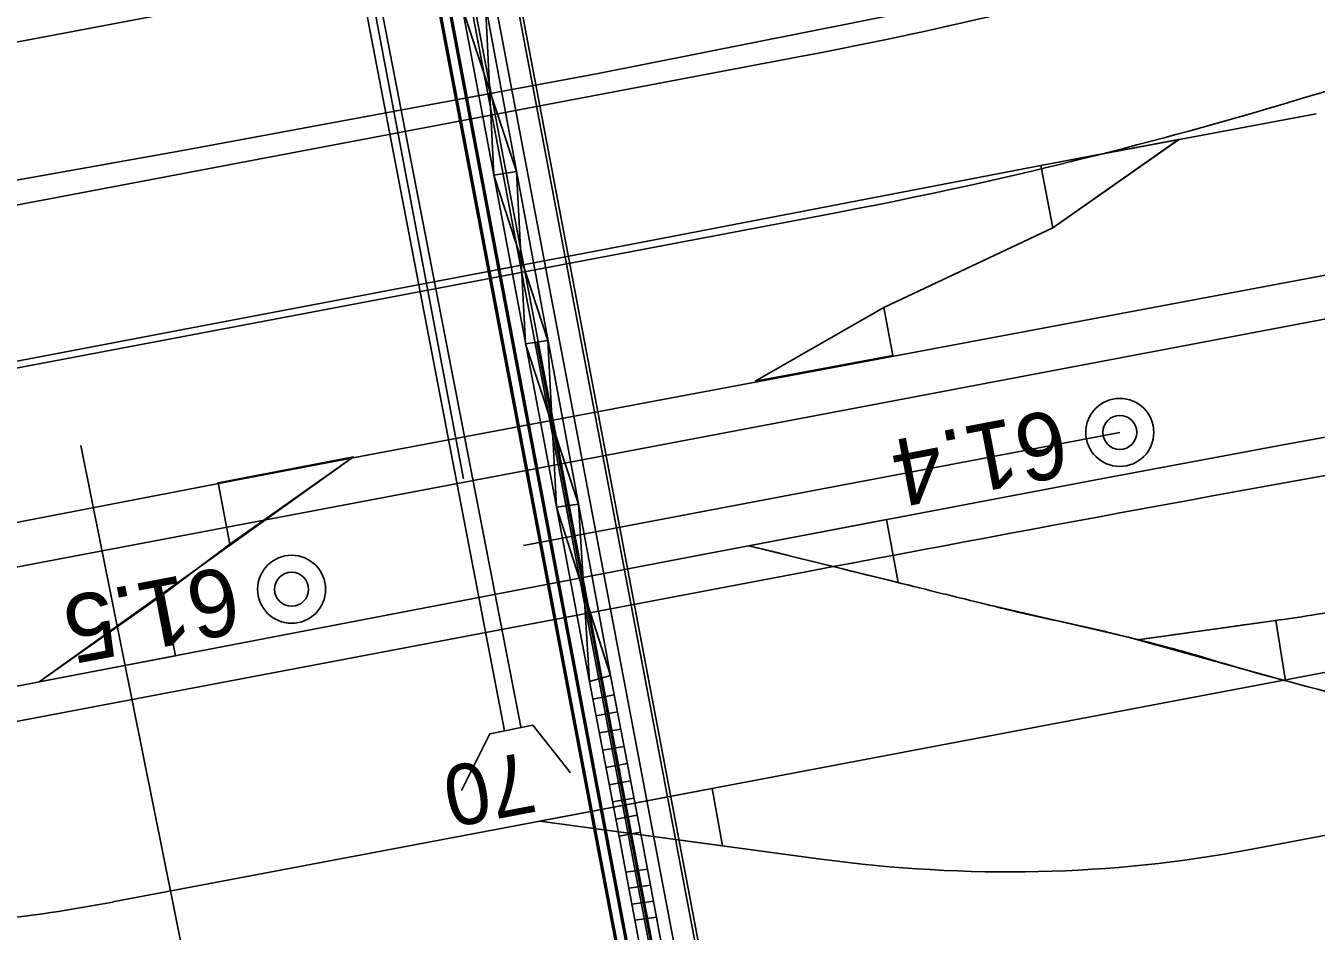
# Model space of a CAD drawing. Extents: x 6541740 to 6566395, y 5525066 to 5530361.
# Drawn here: x 6557192.81 to 6557231.08, y 5526153.77 to 5526180.64 of the extents above; entities that cross this region are included whole.
import ezdxf

# ---------------------------------------------------------------- set-up
doc = ezdxf.new("R2010")
doc.units = 0
for name, color, linetype in [('Domyślna', 7, 'Continuous'), ('TOR_PRZEK_P-komponent', 7, 'Continuous'), ('TOR_PS_OPIS_O-opisy odwodnienia', 7, 'Continuous'), ('TOR_PS_OPIS_T-opis geometrii-wzdluz_cz torowa', 7, 'Continuous'), ('TOR_PS_T-rowy otwarte nieumocnione', 7, 'Continuous'), ('TOR_PS_T-umocnienia skarp', 7, 'Continuous'), ('TOR_RAMKI-ramka+tabelka 1', 7, 'Continuous'), ('TOR_W-warstwa dodatkowa 2', 7, 'Continuous')]:
    doc.layers.add(name, color=color, linetype=linetype)

# ---------------------------------------------------------------- blocks, each defined once
blk = doc.blocks.new('4010_1')
at = {"layer": 'Domyślna'}
for radius in [0.75, 0.375]:
    blk.add_circle((0, 0), radius, dxfattribs=at)

msp = doc.modelspace()

# ---------------------------------------------------------------- linework, layer by layer
at = {"layer": 'Domyślna'}
for p, q in [((6557200.158, 5526195.418), (6557207.01, 5526159.72)), ((6557207.492, 5526159.837), (6557200.574, 5526195.475))]:
    msp.add_line(p, q, dxfattribs=at)
msp.add_lwpolyline([(6557205.727, 5526157.942), (6557206.569, 5526159.63), (6557207.846, 5526159.89), (6557208.96, 5526158.467)], dxfattribs=at)
at = {"layer": 'TOR_PRZEK_P-komponent'}
for p, q in [((6557416.454, 5526207.025), (6557145.327, 5526155.632)), ((6557212.028, 5526183.848), (6557116.502, 5526165.741)), ((6557019.224, 5526142.467), (6557215.881, 5526179.744)), ((6557102.514, 5526153.42), (6557216.785, 5526175.081)), ((6557216.049, 5526164.458), (6556955.024, 5526114.98)), ((6557233.026, 5526161.773), (6557208.044, 5526157.037)), ((6557213.164, 5526158.008), (6557208.055, 5526157.039)), ((6557213.164, 5526158.008), (6557208.055, 5526157.039)), ((6557235.525, 5526157.412), (6557229.122, 5526156.198)), ((6557208.055, 5526157.039), (6557195.39, 5526154.639)), ((6557216.392, 5526155.912), (6557208.055, 5526157.039)), ((6557216.392, 5526155.912), (6557208.055, 5526157.039))]:
    msp.add_line(p, q, dxfattribs=at)
msp.add_lwpolyline([(6557208.055, 5526157.039), (6557213.468, 5526156.307), (6557213.164, 5526158.008)], dxfattribs=at)
msp.add_lwpolyline([(6557208.055, 5526157.039), (6557213.468, 5526156.307), (6557213.164, 5526158.008)], dxfattribs=at)
msp.add_arc((6557599.6, 5524141.009), 2059.479, 100.137444, 100.733239, dxfattribs=at)
for centre, major_axis, start_param, end_param in [((6556815.472, 5528292.13), (-400.409, 2112.386), 3.141593, 3.189176), ((6556816.376, 5528287.466), (-400.409, 2112.386), 3.141593, 3.189174), ((6557116.449, 5526750.613), (-112.673, 594.415), 3.058451, 3.141593), ((6557053.85, 5526901.342), (-141.54, 746.704), 3.102175, 3.141593)]:
    msp.add_ellipse(centre, major_axis=major_axis, ratio=0.25, start_param=start_param, end_param=end_param, dxfattribs=at)
at = {"layer": 'TOR_PS_OPIS_T-opis geometrii-wzdluz_cz torowa'}
for p, q in [((6557205.793, 5526167.193), (6557195.226, 5526222.944)), ((6557207.965, 5526171.251), (6557218.533, 5526115.501)), ((6557225.255, 5526168.573), (6557207.57, 5526165.221)), ((6557194.444, 5526168.185), (6557200.689, 5526137.091)), ((6557194.444, 5526168.185), (6557200.689, 5526137.091))]:
    msp.add_line(p, q, dxfattribs=at)
at = {"layer": 'TOR_PS_T-rowy otwarte nieumocnione'}
for p, q in [((6557231.08, 5526178.023), (6557222.914, 5526176.494)), ((6557231.08, 5526178.023), (6557222.914, 5526176.494)), ((6557226.997, 5526177.259), (6557223.266, 5526174.643)), ((6557226.997, 5526177.259), (6557223.266, 5526174.643)), ((6557223.266, 5526174.643), (6557226.997, 5526177.258)), ((6557223.266, 5526174.643), (6557226.997, 5526177.258)), ((6557214.443, 5526170.092), (6557218.253, 5526172.279)), ((6557214.443, 5526170.092), (6557218.253, 5526172.279)), ((6557214.443, 5526170.092), (6557218.253, 5526172.279)), ((6557214.443, 5526170.092), (6557218.253, 5526172.279)), ((6557202.533, 5526167.843), (6557198.857, 5526165.253)), ((6557202.533, 5526167.843), (6557198.857, 5526165.253)), ((6557193.205, 5526161.17), (6557196.897, 5526163.774)), ((6557193.205, 5526161.17), (6557196.897, 5526163.774)), ((6557225.793, 5526162.417), (6557229.886, 5526162.994)), ((6557225.793, 5526162.417), (6557229.886, 5526162.994))]:
    msp.add_line(p, q, dxfattribs=at)
for points in [[(6557246.51, 5526186.462), (6557234.231, 5526184.137), (6557221.923, 5526181.643), (6557209.734, 5526179.216), (6557197.409, 5526176.929)], [(6557197.409, 5526176.929), (6557209.734, 5526179.216), (6557221.923, 5526181.643), (6557234.231, 5526184.137), (6557246.51, 5526186.462)], [(6557246.51, 5526186.462), (6557234.231, 5526184.137), (6557221.923, 5526181.643), (6557209.734, 5526179.216), (6557197.409, 5526176.929)], [(6557197.409, 5526176.929), (6557209.734, 5526179.216), (6557221.923, 5526181.643), (6557234.231, 5526184.137), (6557246.51, 5526186.462)], [(6557268.852, 5526180.307), (6557260.657, 5526178.76), (6557260.657, 5526178.76), (6557248.388, 5526176.45), (6557248.388, 5526176.449), (6557236.094, 5526174.13), (6557236.094, 5526174.13), (6557223.819, 5526171.819), (6557223.819, 5526171.819), (6557211.543, 5526169.52), (6557211.543, 5526169.52), (6557203.346, 5526167.976), (6557199.25, 5526167.195), (6557199.249, 5526167.195), (6557186.987, 5526164.833), (6557186.987, 5526164.833), (6557174.708, 5526162.516), (6557162.421, 5526160.185), (6557162.421, 5526160.185), (6557150.132, 5526157.846), (6557150.132, 5526157.846), (6557146.037, 5526157.053), (6557137.851, 5526155.44)], [(6557268.852, 5526180.307), (6557260.657, 5526178.76), (6557260.657, 5526178.76), (6557248.388, 5526176.45), (6557248.388, 5526176.449), (6557236.094, 5526174.13), (6557236.094, 5526174.13), (6557223.819, 5526171.819), (6557223.819, 5526171.819), (6557211.543, 5526169.52), (6557211.543, 5526169.52), (6557203.346, 5526167.976), (6557199.25, 5526167.195), (6557199.249, 5526167.195), (6557186.987, 5526164.833), (6557186.987, 5526164.833), (6557174.708, 5526162.516), (6557162.421, 5526160.185), (6557162.421, 5526160.185), (6557150.132, 5526157.846), (6557150.132, 5526157.846), (6557146.037, 5526157.053), (6557137.851, 5526155.44)], [(6557197.409, 5526176.927), (6557185.105, 5526174.736), (6557172.832, 5526172.553), (6557169.344, 5526171.884)], [(6557169.344, 5526171.884), (6557172.832, 5526172.553), (6557185.105, 5526174.736), (6557197.409, 5526176.927)], [(6557197.409, 5526176.927), (6557185.105, 5526174.736), (6557172.832, 5526172.553), (6557169.344, 5526171.884)], [(6557169.344, 5526171.884), (6557172.832, 5526172.553), (6557185.105, 5526174.736), (6557197.409, 5526176.927)], [(6557222.914, 5526176.494), (6557222.914, 5526176.493), (6557210.689, 5526174.139), (6557198.358, 5526171.792)], [(6557222.914, 5526176.494), (6557222.914, 5526176.493), (6557210.689, 5526174.139), (6557198.358, 5526171.792)], [(6557218.253, 5526172.279), (6557223.266, 5526174.643)], [(6557218.253, 5526172.279), (6557223.266, 5526174.643)], [(6557218.253, 5526172.279), (6557223.266, 5526174.643)], [(6557218.253, 5526172.279), (6557223.266, 5526174.643)], [(6557261.875, 5526172.232), (6557259.395, 5526172.099), (6557258.156, 5526172.024), (6557256.301, 5526171.899), (6557253.523, 5526171.679), (6557251.676, 5526171.509), (6557250.753, 5526171.416), (6557249.372, 5526171.266), (6557249.372, 5526171.266), (6557247.987, 5526171.103), (6557247.065, 5526170.987), (6557245.224, 5526170.74), (6557242.468, 5526170.335), (6557240.635, 5526170.047), (6557236.974, 5526169.435), (6557236.974, 5526169.435), (6557232.88, 5526168.711), (6557230.153, 5526168.213), (6557224.703, 5526167.195), (6557212.428, 5526164.865), (6557212.428, 5526164.865), (6557200.161, 5526162.505), (6557200.161, 5526162.505), (6557191.968, 5526160.933)], [(6557261.875, 5526172.232), (6557259.395, 5526172.099), (6557258.156, 5526172.024), (6557256.301, 5526171.899), (6557253.523, 5526171.679), (6557251.676, 5526171.509), (6557250.753, 5526171.416), (6557249.372, 5526171.266), (6557249.372, 5526171.266), (6557247.987, 5526171.103), (6557247.065, 5526170.987), (6557245.224, 5526170.74), (6557242.468, 5526170.335), (6557240.635, 5526170.047), (6557236.974, 5526169.435), (6557236.974, 5526169.435), (6557232.88, 5526168.711), (6557230.153, 5526168.213), (6557224.703, 5526167.195), (6557212.428, 5526164.865), (6557212.428, 5526164.865), (6557200.161, 5526162.505), (6557200.161, 5526162.505), (6557191.968, 5526160.933)], [(6557198.358, 5526171.79), (6557186.11, 5526169.456), (6557173.848, 5526167.145), (6557161.527, 5526164.811), (6557158.117, 5526164.166), (6557158.091, 5526164.161)], [(6557198.358, 5526171.79), (6557186.11, 5526169.456), (6557173.848, 5526167.145), (6557161.527, 5526164.811), (6557158.117, 5526164.166), (6557158.091, 5526164.161)], [(6557193.205, 5526161.17), (6557202.533, 5526167.843)], [(6557193.205, 5526161.17), (6557202.533, 5526167.843)], [(6557196.897, 5526163.774), (6557198.857, 5526165.253)], [(6557196.897, 5526163.774), (6557198.857, 5526165.253)], [(6557221.493, 5526163.424), (6557225.586, 5526162.474), (6557230.173, 5526161.204)], [(6557221.493, 5526163.424), (6557225.586, 5526162.474), (6557230.173, 5526161.204)]]:
    msp.add_lwpolyline(points, dxfattribs=at)
for points in [[(6557226.997, 5526177.259), (6557222.914, 5526176.494), (6557223.266, 5526174.643)], [(6557226.997, 5526177.259), (6557222.914, 5526176.494), (6557223.266, 5526174.643)], [(6557214.443, 5526170.092), (6557218.524, 5526170.857), (6557218.253, 5526172.279)], [(6557214.443, 5526170.092), (6557218.524, 5526170.857), (6557218.253, 5526172.279)], [(6557202.533, 5526167.843), (6557198.511, 5526167.076), (6557198.857, 5526165.253)], [(6557202.533, 5526167.843), (6557198.511, 5526167.076), (6557198.857, 5526165.253)], [(6557214.25, 5526165.21), (6557218.337, 5526165.986), (6557218.685, 5526164.114)], [(6557214.25, 5526165.21), (6557218.337, 5526165.986), (6557218.685, 5526164.114)], [(6557193.206, 5526161.17), (6557197.247, 5526161.946), (6557196.897, 5526163.774)], [(6557193.206, 5526161.17), (6557197.247, 5526161.946), (6557196.897, 5526163.774)], [(6557225.793, 5526162.417), (6557230.173, 5526161.204), (6557229.886, 5526162.994)], [(6557225.793, 5526162.417), (6557230.173, 5526161.204), (6557229.886, 5526162.994)]]:
    msp.add_lwpolyline(points, close=True, dxfattribs=at)
for points in [[(6557250.293, 5526166.395), (6557246.156, 5526165.835), (6557242.019, 5526165.276), (6557237.882, 5526164.716), (6557235.178, 5526164.35), (6557232.588, 5526163.375), (6557229.886, 5526162.994), (6557228.521, 5526162.802), (6557227.157, 5526162.61), (6557225.793, 5526162.417)], [(6557250.293, 5526166.395), (6557246.156, 5526165.835), (6557242.019, 5526165.276), (6557237.882, 5526164.716), (6557235.178, 5526164.35), (6557232.588, 5526163.375), (6557229.886, 5526162.994), (6557228.521, 5526162.802), (6557227.157, 5526162.61), (6557225.793, 5526162.417)], [(6557214.25, 5526165.21), (6557216.616, 5526164.626), (6557218.982, 5526164.041), (6557221.349, 5526163.456), (6557222.765, 5526163.106), (6557224.17, 5526162.828), (6557225.586, 5526162.474), (6557227.108, 5526162.095), (6557228.646, 5526161.615), (6557230.173, 5526161.204), (6557233.093, 5526160.42), (6557236.002, 5526159.7), (6557238.91, 5526158.994), (6557241.136, 5526158.453), (6557243.377, 5526157.837), (6557245.5, 5526157.898), (6557247.623, 5526157.96), (6557249.747, 5526158.022), (6557251.87, 5526158.083)], [(6557214.25, 5526165.21), (6557216.616, 5526164.626), (6557218.982, 5526164.041), (6557221.349, 5526163.456), (6557222.765, 5526163.106), (6557224.17, 5526162.828), (6557225.586, 5526162.474), (6557227.108, 5526162.095), (6557228.646, 5526161.615), (6557230.173, 5526161.204), (6557233.093, 5526160.42), (6557236.002, 5526159.7), (6557238.91, 5526158.994), (6557241.136, 5526158.453), (6557243.377, 5526157.837), (6557245.5, 5526157.898), (6557247.623, 5526157.96), (6557249.747, 5526158.022), (6557251.87, 5526158.083)], [(6557214.25, 5526165.21), (6557216.616, 5526164.626), (6557218.982, 5526164.041), (6557221.349, 5526163.456), (6557222.765, 5526163.106), (6557224.17, 5526162.828), (6557225.586, 5526162.474), (6557227.108, 5526162.095), (6557228.646, 5526161.615), (6557230.173, 5526161.204), (6557233.093, 5526160.42), (6557236.002, 5526159.7), (6557238.91, 5526158.994), (6557241.136, 5526158.453), (6557243.377, 5526157.837), (6557245.5, 5526157.898), (6557247.623, 5526157.96), (6557249.747, 5526158.022), (6557251.87, 5526158.083)], [(6557214.25, 5526165.21), (6557216.616, 5526164.626), (6557218.982, 5526164.041), (6557221.349, 5526163.456), (6557222.765, 5526163.106), (6557224.17, 5526162.828), (6557225.586, 5526162.474), (6557227.108, 5526162.095), (6557228.646, 5526161.615), (6557230.173, 5526161.204), (6557233.093, 5526160.42), (6557236.002, 5526159.7), (6557238.91, 5526158.994), (6557241.136, 5526158.453), (6557243.377, 5526157.837), (6557245.5, 5526157.898), (6557247.623, 5526157.96), (6557249.747, 5526158.022), (6557251.87, 5526158.083)], [(6557214.25, 5526165.21), (6557216.616, 5526164.626), (6557218.982, 5526164.041), (6557221.349, 5526163.456), (6557222.765, 5526163.106), (6557224.17, 5526162.828), (6557225.586, 5526162.474), (6557227.108, 5526162.095), (6557228.646, 5526161.615), (6557230.173, 5526161.204), (6557233.093, 5526160.42), (6557236.002, 5526159.7), (6557238.91, 5526158.994), (6557241.136, 5526158.453), (6557243.377, 5526157.837), (6557245.5, 5526157.898), (6557247.623, 5526157.96), (6557249.747, 5526158.022), (6557251.87, 5526158.083)], [(6557214.25, 5526165.21), (6557216.616, 5526164.626), (6557218.982, 5526164.041), (6557221.349, 5526163.456), (6557222.765, 5526163.106), (6557224.17, 5526162.828), (6557225.586, 5526162.474), (6557227.108, 5526162.095), (6557228.646, 5526161.615), (6557230.173, 5526161.204), (6557233.093, 5526160.42), (6557236.002, 5526159.7), (6557238.91, 5526158.994), (6557241.136, 5526158.453), (6557243.377, 5526157.837), (6557245.5, 5526157.898), (6557247.623, 5526157.96), (6557249.747, 5526158.022), (6557251.87, 5526158.083)]]:
    msp.add_open_spline(points, degree=3, dxfattribs=at)
at = {"layer": 'TOR_PS_T-umocnienia skarp'}
for p, q in [((6557206.69, 5526176.204), (6557207.362, 5526176.315)), ((6557206.69, 5526176.204), (6557207.362, 5526176.315)), ((6557207.633, 5526171.204), (6557208.296, 5526171.298)), ((6557207.633, 5526171.204), (6557208.296, 5526171.298)), ((6557208.549, 5526166.35), (6557209.2, 5526166.446)), ((6557208.549, 5526166.35), (6557209.2, 5526166.446)), ((6557209.625, 5526160.658), (6557210.257, 5526160.788)), ((6557209.625, 5526160.658), (6557210.257, 5526160.788)), ((6557209.72, 5526160.164), (6557210.355, 5526160.28)), ((6557209.72, 5526160.164), (6557210.355, 5526160.28)), ((6557209.819, 5526159.653), (6557210.453, 5526159.769)), ((6557209.819, 5526159.653), (6557210.453, 5526159.769)), ((6557209.917, 5526159.141), (6557210.551, 5526159.257)), ((6557209.917, 5526159.141), (6557210.551, 5526159.257)), ((6557210.016, 5526158.629), (6557210.649, 5526158.746)), ((6557210.016, 5526158.629), (6557210.649, 5526158.746)), ((6557210.114, 5526158.117), (6557210.747, 5526158.234)), ((6557210.114, 5526158.117), (6557210.747, 5526158.234)), ((6557210.212, 5526157.606), (6557210.846, 5526157.722)), ((6557210.212, 5526157.606), (6557210.846, 5526157.722)), ((6557210.311, 5526157.094), (6557210.944, 5526157.211)), ((6557210.311, 5526157.094), (6557210.944, 5526157.211)), ((6557211.041, 5526156.706), (6557210.408, 5526156.59)), ((6557211.041, 5526156.706), (6557210.408, 5526156.59)), ((6557210.607, 5526155.519), (6557211.245, 5526155.609)), ((6557210.607, 5526155.519), (6557211.245, 5526155.609)), ((6557210.694, 5526155.051), (6557211.333, 5526155.139)), ((6557210.694, 5526155.051), (6557211.333, 5526155.139)), ((6557210.784, 5526154.574), (6557211.421, 5526154.666)), ((6557210.784, 5526154.574), (6557211.421, 5526154.666)), ((6557210.872, 5526154.102), (6557211.51, 5526154.193)), ((6557210.872, 5526154.102), (6557211.51, 5526154.193))]:
    msp.add_line(p, q, dxfattribs=at)
for points in [[(6557209.524, 5526161.186), (6557202.872, 5526196.437), (6557203.594, 5526196.546)], [(6557209.524, 5526161.186), (6557202.872, 5526196.437), (6557203.594, 5526196.546)], [(6557203.594, 5526196.546), (6557203.824, 5526191.392), (6557205.487, 5526186.383), (6557205.745, 5526181.211), (6557207.362, 5526176.315), (6557207.633, 5526171.204), (6557209.2, 5526166.446), (6557209.524, 5526161.186)], [(6557209.524, 5526161.186), (6557210.148, 5526161.357), (6557203.594, 5526196.546)], [(6557203.594, 5526196.546), (6557203.824, 5526191.392), (6557205.487, 5526186.383), (6557205.745, 5526181.211), (6557207.362, 5526176.315), (6557207.633, 5526171.204), (6557209.2, 5526166.446), (6557209.524, 5526161.186)], [(6557209.524, 5526161.186), (6557210.148, 5526161.357), (6557203.594, 5526196.546)], [(6557210.148, 5526161.357), (6557208.549, 5526166.35), (6557208.296, 5526171.298), (6557206.69, 5526176.204), (6557206.444, 5526181.244), (6557204.787, 5526186.286), (6557204.528, 5526191.53), (6557202.872, 5526196.437)], [(6557210.148, 5526161.357), (6557208.549, 5526166.35), (6557208.296, 5526171.298), (6557206.69, 5526176.204), (6557206.444, 5526181.244), (6557204.787, 5526186.286), (6557204.528, 5526191.53), (6557202.872, 5526196.437)], [(6557210.148, 5526161.357), (6557211.041, 5526156.706), (6557211.245, 5526155.609), (6557212.038, 5526151.367), (6557212.295, 5526149.991), (6557213.131, 5526145.502)], [(6557210.148, 5526161.357), (6557211.041, 5526156.706), (6557211.245, 5526155.609), (6557212.038, 5526151.367), (6557212.295, 5526149.991), (6557213.131, 5526145.502)], [(6557209.524, 5526161.186), (6557210.408, 5526156.59), (6557210.607, 5526155.519), (6557211.401, 5526151.272), (6557211.658, 5526149.901), (6557212.492, 5526145.415)], [(6557209.524, 5526161.186), (6557210.408, 5526156.59), (6557210.607, 5526155.519), (6557211.401, 5526151.272), (6557211.658, 5526149.901), (6557212.492, 5526145.415)]]:
    msp.add_lwpolyline(points, dxfattribs=at)
at = {"layer": 'TOR_W-warstwa dodatkowa 2'}
for p, q in [((6557202.388, 5526204.28), (6557212.551, 5526150.653)), ((6557202.388, 5526204.28), (6557212.551, 5526150.653)), ((6557201.676, 5526204.146), (6557211.743, 5526151.021)), ((6557201.676, 5526204.146), (6557211.743, 5526151.021)), ((6557201.774, 5526204.164), (6557211.855, 5526150.97)), ((6557201.774, 5526204.164), (6557211.855, 5526150.97)), ((6557202.885, 5526192.552), (6557210.775, 5526150.925)), ((6557202.885, 5526192.552), (6557210.775, 5526150.925)), ((6557202.934, 5526192.562), (6557210.825, 5526150.934)), ((6557202.934, 5526192.562), (6557210.825, 5526150.934)), ((6557203.18, 5526192.608), (6557211.07, 5526150.981)), ((6557203.18, 5526192.608), (6557211.07, 5526150.981)), ((6557203.229, 5526192.618), (6557211.119, 5526150.99)), ((6557203.229, 5526192.618), (6557211.119, 5526150.99)), ((6557205.423, 5526191.624), (6557212.837, 5526152.504)), ((6557205.423, 5526191.624), (6557212.837, 5526152.504)), ((6557205.596, 5526191.249), (6557212.867, 5526152.882)), ((6557205.596, 5526191.249), (6557212.867, 5526152.882))]:
    msp.add_line(p, q, dxfattribs=at)

# ---------------------------------------------------------------- block references
at = {"layer": 'TOR_RAMKI-ramka+tabelka 1', "xscale": 1.345963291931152, "yscale": 1.345963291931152}
for p in [(6557225.255, 5526168.573), (6557200.693, 5526163.917)]:
    msp.add_blockref('4010_1', p, dxfattribs=at)

# ---------------------------------------------------------------- texts
at = {"layer": 'TOR_PS_OPIS_O-opisy odwodnienia'}
msp.add_text('70', height=1.8, rotation=190.7332, dxfattribs=at).set_placement((6557207.707, 5526159.108))
at = {"layer": 'TOR_RAMKI-ramka+tabelka 1'}
for s, p in [('61.4', (6557223.477, 5526169.28)), ('61.5', (6557198.922, 5526164.625))]:
    msp.add_text(s, height=2, rotation=190.7691, dxfattribs=at).set_placement(p)

doc.saveas('drawing.dxf')
